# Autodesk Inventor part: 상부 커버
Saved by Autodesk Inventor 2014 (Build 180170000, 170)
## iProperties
Created: 2026-08
Part Number: 상부 커버
Material: 알루미늄 6061
Document SubType Name: Modeling
Designer: dg
Density: 2.71 g/cm^3
Appearance: 알루미늄 - 평지
Mass: 46.3484 g
Surface Area: 69.3745 cm^2
Volume: 17.1027 cm^3
Author: jhkim
Creation Date: 2026-07-31
Sending System: Autodesk Inventor 2027
Preprocessor: ST-DEVELOPER v20.1
Author: dg
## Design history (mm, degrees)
node "상부 커버1"
node "솔리드1"
node "기준1"
